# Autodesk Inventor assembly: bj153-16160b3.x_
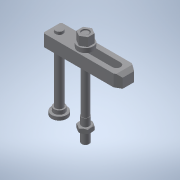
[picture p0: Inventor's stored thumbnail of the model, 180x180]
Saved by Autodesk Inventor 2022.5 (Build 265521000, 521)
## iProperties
Part Number: bj153-16160b3.x_
Material: 一般
Document SubType Name: Assembly
Designer: ImaoCorp
Sending System: SOLIDWORKS 2017-2017317
MC: AMD64
MC_MODEL: Intel64 Family 6 Model 60 Stepping 3, GenuineIntel
OS: Windows_NT
FRU: Parasolid Version 29.0, build 201,  4-17-2017
FORMAT: text
GUISE: transmit
KEY: bj153-16160b3
FILE: bj153-16160b3.x_t
DATE: Fri Mar 15 10:22:42 2019
Author: ImaoCorp
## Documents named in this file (6)
- X:\14_SW2022-Inv2022\00_全2023-1023新製品(TCC)まで\b\bj153-16160b3\BJ153-16160B3.iam
- X:\14_SW2022-Inv2022\00_全2023-1023新製品(TCC)まで\b\bj153-16160b3\bj153-16160b3_01.ipt
- X:\14_SW2022-Inv2022\00_全2023-1023新製品(TCC)まで\b\bj153-16160b3\bj153-16160b3_02.ipt
- X:\14_SW2022-Inv2022\00_全2023-1023新製品(TCC)まで\b\bj153-16160b3\bj153-16160b3_03.ipt
- X:\14_SW2022-Inv2022\00_全2023-1023新製品(TCC)まで\b\bj153-16160b3\bj153-16160b3_04.ipt
- X:\14_SW2022-Inv2022\00_全2023-1023新製品(TCC)まで\b\bj153-16160b3\bj153-16160b3_05.ipt
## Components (5 placed, 5 different names)
1. bj153-16160b3_01
2. bj153-16160b3_02
3. bj153-16160b3_03
4. bj153-16160b3_04
5. bj153-16160b3_05
